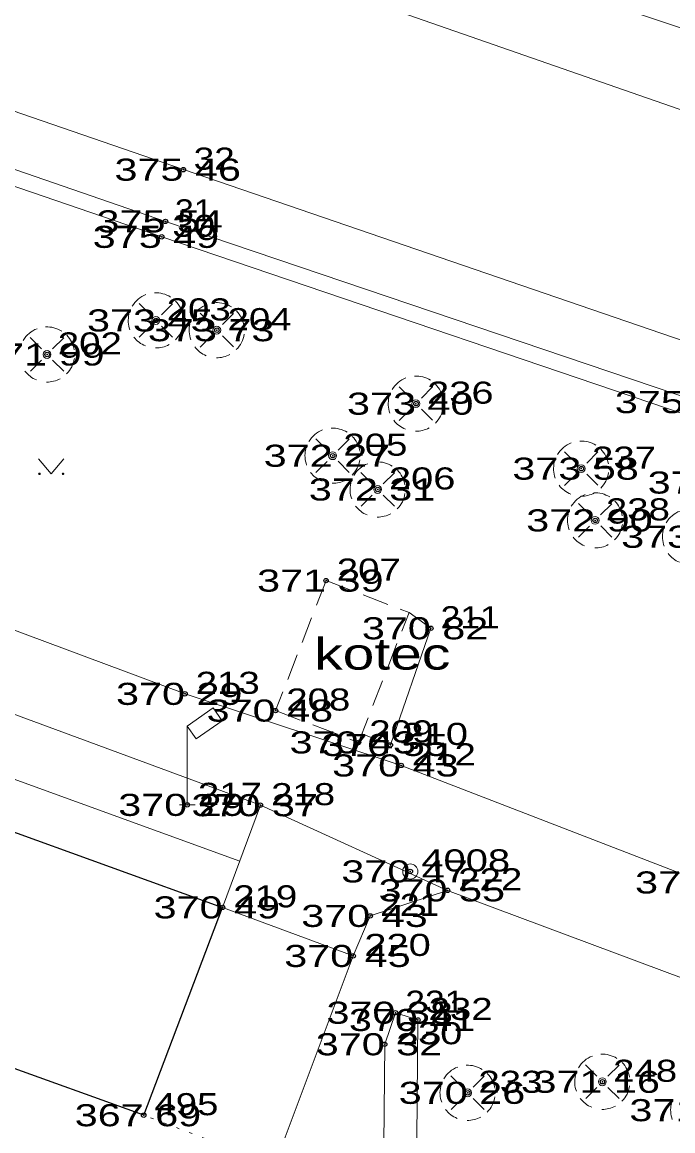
# Model space of a CAD drawing. Extents: x -789669 to -789458, y -977587 to -977420.
# Drawn here: x -789549.89 to -789529.27, y -977497.54 to -977462.39 of the extents above; entities that cross this region are included whole.
import ezdxf
from ezdxf.enums import TextEntityAlignment as Align

# ---------------------------------------------------------------- set-up
doc = ezdxf.new("R2010")
doc.units = 0
doc.header["$LTSCALE"] = 0.28
doc.header["$PDMODE"] = 32
doc.header["$PDSIZE"] = 0.14
doc.linetypes.add('DOTTED', pattern=[1.5, 0.3, -1.2])
doc.linetypes.add('MEDIUM_DASHED', pattern=[4.5, 3, -1.5])
for name, color, linetype, lineweight in [('1', 7, 'Continuous', 13), ('2', 7, 'Continuous', 13), ('3', 7, 'Continuous', 13), ('33', 7, 'Continuous', 13), ('4', 7, 'Continuous', 13), ('50', 7, 'Continuous', 13), ('9', 7, 'Continuous', 25)]:
    doc.layers.add(name, color=color, linetype=linetype, lineweight=lineweight)
for name, color, linetype in [('5', 7, 'Continuous'), ('57', 7, 'Continuous'), ('58', 7, 'Continuous'), ('59', 7, 'Continuous')]:
    doc.layers.add(name, color=color, linetype=linetype)

msp = doc.modelspace()

# ---------------------------------------------------------------- linework, layer by layer
at = {"layer": '1'}
for p, q in [((-789542.996, -977488.992), (-789568.925, -977479.592)), ((-789539.125, -977484.959), (-789538.22, -977485.31))]:
    msp.add_line(p, q, dxfattribs=at)
for points in [[(-789652.33, -977422.61), (-789627.98, -977430.97), (-789609.02, -977437.54), (-789583.63, -977446.35), (-789563.97, -977453.25), (-789542.04, -977460.63), (-789524.21, -977466.84), (-789507.23, -977472.64), (-789487.17, -977479.36)], [(-789509.64, -977479.12), (-789526.32, -977473.4), (-789544.78, -977467.07), (-789566.2, -977459.68), (-789586.28, -977452.77), (-789604.78, -977446.41), (-789630.61, -977437.53), (-789654.9, -977429.37)], [(-789604.26, -977448.38), (-789586.79, -977454.41), (-789566.59, -977461.37), (-789545.35, -977468.71), (-789526.33, -977475.15), (-789510.21, -977480.66), (-789489.34, -977487.73), (-789463.94, -977496.44)], [(-789591.43, -977469.4), (-789579.77, -977473.66), (-789573.29, -977476.09), (-789568.3, -977477.84), (-789563.66, -977479.48), (-789554.46, -977482.75), (-789542.34, -977487.22), (-789543.54, -977490.46)], [(-789528.28, -977489.67), (-789537.88, -977485.96), (-789544.73, -977483.69), (-789553.55, -977480.4), (-789562.72, -977477.06), (-789579.25, -977471.12)], [(-789538.22, -977485.31), (-789536.94, -977481.61), (-789537.63, -977481.11)], [(-789542.34, -977487.22), (-789536.41, -977489.92), (-789524.32, -977494.44)], [(-789536.41, -977489.92), (-789538.86, -977490.73), (-789539.4, -977492)]]:
    msp.add_lwpolyline(points, dxfattribs=at)
msp.add_lwpolyline([(-789538.06, -977493.8), (-789538.4, -977494.8), (-789538.46, -977501.15), (-789537.41, -977501.6), (-789537.35, -977494.03)], close=True, dxfattribs=at)
at = {"layer": '2'}
msp.add_lwpolyline([(-789651.99, -977420.32), (-789627.42, -977429.7), (-789608.58, -977435.72), (-789582.71, -977444.73), (-789563.37, -977451.38), (-789541.29, -977458.45), (-789523.64, -977464.38), (-789506.63, -977471.11), (-789487.17, -977479.36)], dxfattribs=at)
at = {"layer": '3'}
for points in [[(-789601.84, -977457.06), (-789598.55, -977450.95), (-789566.5, -977461.99), (-789545.47, -977469.2), (-789526.54, -977475.63), (-789520.95, -977477.5)], [(-789543.54, -977490.46), (-789539.4, -977492), (-789542.51, -977500.28)]]:
    msp.add_lwpolyline(points, dxfattribs=at)
at = {"layer": '33'}
for p, q in [((-789544.66, -977484.71), (-789544.66, -977487.21)), ((-789544.91, -977487.21), (-789544.41, -977487.21))]:
    msp.add_line(p, q, dxfattribs=at)
msp.add_lwpolyline([(-789544.66, -977484.71), (-789543.84, -977484.137), (-789543.554, -977484.547), (-789544.374, -977485.12)], close=True, dxfattribs=at)
at = {"layer": '4'}
for p, q in [((-789546.184, -977471.312), (-789545.827, -977471.668)), ((-789545.124, -977471.32), (-789545.477, -977471.673)), ((-789544.254, -977471.622), (-789543.897, -977471.978)), ((-789543.194, -977471.63), (-789543.547, -977471.983)), ((-789546.18, -977472.383), (-789545.828, -977472.032)), ((-789545.65, -977471.856), (-789545.65, -977471.844)), ((-789545.476, -977472.027), (-789545.124, -977472.377)), ((-789543.72, -977472.166), (-789543.72, -977472.154)), ((-789549.634, -977472.392), (-789549.277, -977472.748)), ((-789548.574, -977472.4), (-789548.927, -977472.753)), ((-789544.25, -977472.693), (-789543.898, -977472.342)), ((-789543.546, -977472.337), (-789543.194, -977472.687)), ((-789549.63, -977473.463), (-789549.278, -977473.112)), ((-789549.1, -977472.936), (-789549.1, -977472.924)), ((-789548.926, -977473.107), (-789548.574, -977473.457)), ((-789537.944, -977473.952), (-789537.587, -977474.308)), ((-789536.884, -977473.96), (-789537.237, -977474.313)), ((-789537.41, -977474.496), (-789537.41, -977474.484)), ((-789537.94, -977475.023), (-789537.588, -977474.672)), ((-789537.236, -977474.667), (-789536.884, -977475.017)), ((-789540.584, -977475.602), (-789540.227, -977475.958)), ((-789539.524, -977475.61), (-789539.877, -977475.963)), ((-789532.704, -977476.012), (-789532.347, -977476.368)), ((-789531.644, -977476.02), (-789531.997, -977476.373)), ((-789540.58, -977476.673), (-789540.228, -977476.322)), ((-789540.05, -977476.146), (-789540.05, -977476.134)), ((-789539.876, -977476.317), (-789539.524, -977476.667)), ((-789539.154, -977476.672), (-789538.797, -977477.028)), ((-789538.094, -977476.68), (-789538.447, -977477.033)), ((-789532.7, -977477.083), (-789532.348, -977476.732)), ((-789532.17, -977476.556), (-789532.17, -977476.544)), ((-789531.996, -977476.727), (-789531.644, -977477.077)), ((-789539.15, -977477.743), (-789538.798, -977477.392)), ((-789538.62, -977477.216), (-789538.62, -977477.204)), ((-789538.446, -977477.387), (-789538.094, -977477.737)), ((-789532.264, -977477.652), (-789531.907, -977478.008)), ((-789531.204, -977477.66), (-789531.557, -977478.013)), ((-789532.26, -977478.723), (-789531.908, -977478.372)), ((-789531.73, -977478.196), (-789531.73, -977478.184)), ((-789531.556, -977478.367), (-789531.204, -977478.717)), ((-789532.034, -977495.452), (-789531.677, -977495.808)), ((-789530.974, -977495.46), (-789531.327, -977495.813)), ((-789536.304, -977495.802), (-789535.947, -977496.158)), ((-789535.244, -977495.81), (-789535.597, -977496.163)), ((-789531.5, -977495.996), (-789531.5, -977495.984)), ((-789535.77, -977496.346), (-789535.77, -977496.334)), ((-789532.03, -977496.523), (-789531.678, -977496.172)), ((-789531.326, -977496.167), (-789530.974, -977496.517)), ((-789536.3, -977496.873), (-789535.948, -977496.522)), ((-789535.596, -977496.517), (-789535.244, -977496.867))]:
    msp.add_line(p, q, dxfattribs=at)
for points in [[(-789549.371, -977476.236), (-789548.969, -977476.715), (-789548.567, -977476.236)], [(-789549.343, -977476.692), (-789549.329, -977476.7), (-789549.324, -977476.715), (-789549.33, -977476.728), (-789549.343, -977476.736), (-789549.359, -977476.728), (-789549.365, -977476.715), (-789549.361, -977476.701), (-789549.35, -977476.695), (-789549.335, -977476.701), (-789549.33, -977476.715), (-789549.333, -977476.725), (-789549.343, -977476.73), (-789549.354, -977476.725), (-789549.36, -977476.714), (-789549.355, -977476.704), (-789549.35, -977476.701), (-789549.339, -977476.705), (-789549.334, -977476.715), (-789549.34, -977476.722), (-789549.348, -977476.72), (-789549.353, -977476.712), (-789549.348, -977476.707), (-789549.34, -977476.711), (-789549.343, -977476.715)], [(-789548.593, -977476.693), (-789548.579, -977476.701), (-789548.574, -977476.716), (-789548.58, -977476.729), (-789548.593, -977476.737), (-789548.609, -977476.729), (-789548.615, -977476.716), (-789548.611, -977476.702), (-789548.6, -977476.696), (-789548.585, -977476.702), (-789548.58, -977476.716), (-789548.583, -977476.726), (-789548.593, -977476.731), (-789548.604, -977476.726), (-789548.61, -977476.715), (-789548.605, -977476.705), (-789548.6, -977476.702), (-789548.589, -977476.706), (-789548.584, -977476.716), (-789548.59, -977476.723), (-789548.598, -977476.721), (-789548.603, -977476.713), (-789548.598, -977476.708), (-789548.59, -977476.712), (-789548.593, -977476.716)]]:
    msp.add_lwpolyline(points, dxfattribs=at)
for centre, radius in [((-789545.6539, -977471.8494), 0.125), ((-789543.7239, -977472.1594), 0.125), ((-789549.1039, -977472.9294), 0.125), ((-789537.4139, -977474.4894), 0.125), ((-789540.0539, -977476.1394), 0.125), ((-789549.344, -977476.715), 0.025), ((-789548.594, -977476.715), 0.025), ((-789532.1739, -977476.5494), 0.125), ((-789538.6239, -977477.2094), 0.125), ((-789531.7339, -977478.1894), 0.125), ((-789531.5039, -977495.9894), 0.125), ((-789535.7739, -977496.3394), 0.125)]:
    msp.add_circle(centre, radius, dxfattribs=at)
for centre, start, end in [((-789545.6539, -977471.8494), 111.04924, 149.34666), ((-789545.6539, -977471.8494), 57.94289, 92.85253), ((-789545.6539, -977471.8494), 9.68453, 44.47714), ((-789543.7239, -977472.1594), 111.04924, 149.34666), ((-789543.7239, -977472.1594), 57.94289, 92.85253), ((-789545.6539, -977471.8494), 166.76695, 200.11735), ((-789543.7239, -977472.1594), 9.68453, 44.47714), ((-789549.1039, -977472.9294), 111.04924, 149.34666), ((-789549.1039, -977472.9294), 57.94289, 92.85253), ((-789545.6539, -977471.8494), 315.09105, 351.67435), ((-789543.7239, -977472.1594), 166.76695, 200.11735), ((-789549.1039, -977472.9294), 9.68453, 44.47714), ((-789545.6539, -977471.8494), 217.06959, 247.69959), ((-789543.7239, -977472.1594), 315.09105, 351.67435), ((-789545.6539, -977471.8494), 269.18965, 298.56841), ((-789543.7239, -977472.1594), 217.06959, 247.69959), ((-789549.1039, -977472.9294), 315.09105, 351.67435), ((-789543.7239, -977472.1594), 269.18965, 298.56841), ((-789549.1039, -977472.9294), 217.06959, 247.69959), ((-789549.1039, -977472.9294), 269.18965, 298.56841), ((-789537.4139, -977474.4894), 111.04924, 149.34666), ((-789537.4139, -977474.4894), 57.94289, 92.85253), ((-789537.4139, -977474.4894), 9.68453, 44.47714), ((-789537.4139, -977474.4894), 166.76695, 200.11735), ((-789537.4139, -977474.4894), 315.09105, 351.67435), ((-789540.0539, -977476.1394), 111.04924, 149.34666), ((-789540.0539, -977476.1394), 57.94289, 92.85253), ((-789537.4139, -977474.4894), 217.06959, 247.69959), ((-789537.4139, -977474.4894), 269.18965, 298.56841), ((-789540.0539, -977476.1394), 9.68453, 44.47714), ((-789532.1739, -977476.5494), 57.94289, 92.85253), ((-789540.0539, -977476.1394), 166.76695, 200.11735), ((-789532.1739, -977476.5494), 111.04924, 149.34666), ((-789532.1739, -977476.5494), 9.68453, 44.47714), ((-789540.0539, -977476.1394), 315.09105, 351.67435), ((-789538.6239, -977477.2094), 111.04924, 149.34666), ((-789538.6239, -977477.2094), 57.94289, 92.85253), ((-789532.1739, -977476.5494), 166.76695, 200.11735), ((-789540.0539, -977476.1394), 217.06959, 247.69959), ((-789538.6239, -977477.2094), 9.68453, 44.47714), ((-789532.1739, -977476.5494), 315.09105, 351.67435), ((-789540.0539, -977476.1394), 269.18965, 298.56841), ((-789538.6239, -977477.2094), 166.76695, 200.11735), ((-789532.1739, -977476.5494), 217.06959, 247.69959), ((-789538.6239, -977477.2094), 315.09105, 351.67435), ((-789531.7339, -977478.1894), 111.04924, 149.34666), ((-789532.1739, -977476.5494), 269.18965, 298.56841), ((-789531.7339, -977478.1894), 57.94289, 92.85253), ((-789538.6239, -977477.2094), 217.06959, 247.69959), ((-789531.7339, -977478.1894), 9.68453, 44.47714), ((-789538.6239, -977477.2094), 269.18965, 298.56841), ((-789531.7339, -977478.1894), 166.76695, 200.11735), ((-789528.7239, -977478.7094), 111.04924, 149.34666), ((-789531.7339, -977478.1894), 315.09105, 351.67435), ((-789531.7339, -977478.1894), 217.06959, 247.69959), ((-789528.7239, -977478.7094), 166.76695, 200.11735), ((-789531.7339, -977478.1894), 269.18965, 298.56841), ((-789528.7239, -977478.7094), 217.06959, 247.69959), ((-789531.5039, -977495.9894), 111.04924, 149.34666), ((-789531.5039, -977495.9894), 57.94289, 92.85253), ((-789531.5039, -977495.9894), 9.68453, 44.47714), ((-789535.7739, -977496.3394), 111.04924, 149.34666), ((-789535.7739, -977496.3394), 57.94289, 92.85253), ((-789535.7739, -977496.3394), 9.68453, 44.47714), ((-789531.5039, -977495.9894), 166.76695, 200.11735), ((-789535.7739, -977496.3394), 166.76695, 200.11735), ((-789531.5039, -977495.9894), 315.09105, 351.67435), ((-789535.7739, -977496.3394), 315.09105, 351.67435), ((-789531.5039, -977495.9894), 217.06959, 247.69959), ((-789531.5039, -977495.9894), 269.18965, 298.56841), ((-789528.4639, -977496.8894), 166.76695, 200.11735), ((-789535.7739, -977496.3394), 217.06959, 247.69959), ((-789535.7739, -977496.3394), 269.18965, 298.56841)]:
    msp.add_arc(centre, 0.875, start, end, dxfattribs=at)
at = {"layer": '50'}
msp.add_line((-789537.598, -977489.32), (-789537.582, -977489.32), dxfattribs=at)
msp.add_circle((-789537.5898, -977489.3205), 0.24, dxfattribs=at)
at = {"layer": '57'}
for p in [(-789544.78, -977467.07), (-789545.35, -977468.71), (-789545.47, -977469.2), (-789545.65, -977471.85), (-789543.72, -977472.16), (-789549.1, -977472.93), (-789537.41, -977474.49), (-789540.05, -977476.14), (-789532.17, -977476.55), (-789538.62, -977477.21), (-789531.73, -977478.19), (-789540.26, -977480.1), (-789536.94, -977481.61), (-789544.73, -977483.69), (-789541.86, -977484.22), (-789539.23, -977485.23), (-789538.22, -977485.31), (-789537.88, -977485.96), (-789544.66, -977487.21), (-789542.34, -977487.22), (-789537.59, -977489.32), (-789536.41, -977489.92), (-789543.54, -977490.46), (-789538.86, -977490.73), (-789539.4, -977492), (-789538.06, -977493.8), (-789537.35, -977494.03), (-789538.4, -977494.8), (-789531.5, -977495.99), (-789535.77, -977496.34), (-789546.04, -977497.05)]:
    msp.add_point(p, dxfattribs=at)
at = {"layer": '9'}
for p, q in [((-789592.9, -977472.67), (-789543.54, -977490.46)), ((-789546.04, -977497.05), (-789596.85, -977478.72)), ((-789546.04, -977497.05), (-789543.54, -977490.46))]:
    msp.add_line(p, q, dxfattribs=at)
at = {"layer": '9', "linetype": 'MEDIUM_DASHED', "lineweight": 13}
for p in [(-789540.26, -977480.1), (-789539.23, -977485.23)]:
    msp.add_line(p, (-789537.63, -977481.11), dxfattribs=at)
at = {"layer": '9', "linetype": 'DOTTED', "lineweight": 13}
msp.add_line((-789542.465, -977498.406), (-789546.04, -977497.05), dxfattribs=at)
at = {"layer": '9', "linetype": 'MEDIUM_DASHED', "lineweight": 13}
msp.add_lwpolyline([(-789540.26, -977480.1), (-789541.86, -977484.22), (-789539.23, -977485.23)], dxfattribs=at)

# ---------------------------------------------------------------- texts
at = {"layer": '5', "width": 1.35}
msp.add_text('kotec', height=1, dxfattribs=at).set_placement((-789540.637, -977482.922))
at = {"layer": '50', "width": 1.35}
msp.add_text(' 4008', height=0.7, dxfattribs=at).set_placement((-789537.59, -977489.32))
at = {"layer": '58'}
for s, width, p in [(' 32', 1.25, (-789544.78, -977467.07)), (' 31', 1.15, (-789545.35, -977468.71)), (' 30', 1.3, (-789545.47, -977469.2)), (' 203', 1.3, (-789545.65, -977471.85)), (' 204', 1.3, (-789543.72, -977472.16)), (' 202', 1.3, (-789549.1, -977472.93)), (' 236', 1.35, (-789537.41, -977474.49)), (' 205', 1.3, (-789540.05, -977476.14)), (' 237', 1.3, (-789532.17, -977476.55)), (' 206', 1.35, (-789538.62, -977477.21)), (' 238', 1.3, (-789531.73, -977478.19)), (' 207', 1.3, (-789540.26, -977480.1)), (' 211', 1.2, (-789536.94, -977481.61)), (' 213', 1.3, (-789544.73, -977483.69)), (' 208', 1.3, (-789541.86, -977484.22)), (' 209', 1.3, (-789539.23, -977485.23)), (' 210', 1.35, (-789538.22, -977485.31)), (' 212', 1.3, (-789537.88, -977485.96)), (' 217', 1.3, (-789544.66, -977487.21)), (' 218', 1.3, (-789542.34, -977487.22)), (' 4008', 1.35, (-789537.59, -977489.32)), (' 222', 1.3, (-789536.41, -977489.92)), (' 219', 1.3, (-789543.54, -977490.46)), (' 221', 1.2, (-789538.86, -977490.73)), (' 220', 1.35, (-789539.4, -977492)), (' 231', 1.2, (-789538.06, -977493.8)), (' 232', 1.3, (-789537.35, -977494.03)), (' 230', 1.35, (-789538.4, -977494.8)), (' 248', 1.3, (-789531.5, -977495.99)), (' 233', 1.3, (-789535.77, -977496.34)), (' 495', 1.3, (-789546.04, -977497.05))]:
    msp.add_text(s, height=0.7, dxfattribs=dict(at, width=width)).set_placement(p)
at = {"layer": '59', "width": 1.4}
for s, p in [('375 46 ', (-789544.78, -977467.42)), ('375 54 ', (-789545.35, -977469.06)), ('375 49 ', (-789545.47, -977469.55)), ('373 45 ', (-789545.65, -977472.2)), ('373 73 ', (-789543.72, -977472.51)), ('371 99 ', (-789549.1, -977473.28)), ('373 40 ', (-789537.41, -977474.84)), ('375 63 ', (-789528.92, -977474.79)), ('372 27 ', (-789540.05, -977476.49)), ('373 58 ', (-789532.17, -977476.9)), ('374 50 ', (-789527.88, -977477.34)), ('372 31 ', (-789538.62, -977477.56)), ('372 90 ', (-789531.73, -977478.54)), ('373 32 ', (-789528.72, -977479.06)), ('371 39 ', (-789540.26, -977480.45)), ('370 82 ', (-789536.94, -977481.96)), ('370 29 ', (-789544.73, -977484.04)), ('370 48 ', (-789541.86, -977484.57)), ('370 43 ', (-789539.23, -977485.58)), ('370 55 ', (-789538.22, -977485.66)), ('370 43 ', (-789537.88, -977486.31)), ('370 29 ', (-789544.66, -977487.56)), ('370 37 ', (-789542.34, -977487.57)), ('370 47 ', (-789537.59, -977489.67)), ('371 21 ', (-789528.28, -977490.02)), ('370 55 ', (-789536.41, -977490.27)), ('370 49 ', (-789543.54, -977490.81)), ('370 43 ', (-789538.86, -977491.08)), ('370 45 ', (-789539.4, -977492.35)), ('370 38 ', (-789538.06, -977494.15)), ('370 41 ', (-789537.35, -977494.38)), ('370 32 ', (-789538.4, -977495.15)), ('371 16 ', (-789531.5, -977496.34)), ('370 26 ', (-789535.77, -977496.69)), ('367 69 ', (-789546.04, -977497.4)), ('371 27 ', (-789528.46, -977497.24))]:
    msp.add_text(s, height=0.7, dxfattribs=at).set_placement(p, align=Align.CENTER)

doc.saveas('drawing.dxf')
